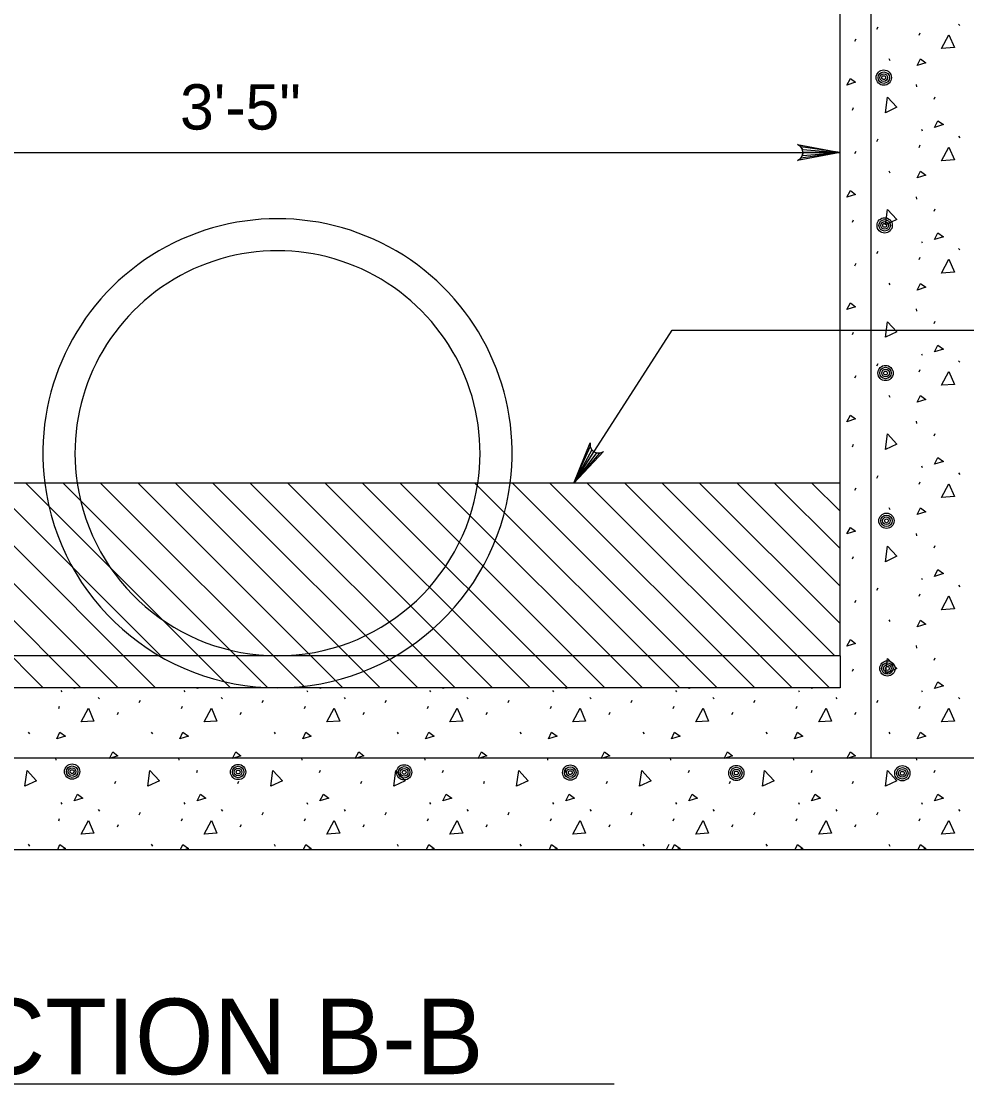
# Model space of a CAD drawing. Extents: x 2.4 to 9.7, y 1.1 to 11.2.
# Drawn here: x 3.407 to 4.657, y 8.252 to 9.657 of the extents above; entities that cross this region are included whole.
import ezdxf

# ---------------------------------------------------------------- set-up
doc = ezdxf.new("R2010")
doc.units = 0
for name, color, linetype in [('DETL-DIMS', 7, 'Continuous'), ('DETL-LINE', 7, 'Continuous'), ('DETL-NOTE', 7, 'Continuous'), ('DETL-PATT', 7, 'Continuous'), ('DETL-TITL', 7, 'Continuous')]:
    doc.layers.add(name, color=color, linetype=linetype)

msp = doc.modelspace()

# ---------------------------------------------------------------- linework, layer by layer
at = {"layer": 'DETL-DIMS'}
for p, q in [((3.0173, 9.4838), (4.49, 9.4838)), ((4.1377, 9.0465), (4.2679, 9.2486)), ((4.2679, 9.2486), (4.7805, 9.2486)), ((3.6529, 8.8182), (2.5069, 8.8182))]:
    msp.add_line(p, q, dxfattribs=at)
for points in [[(4.49, 9.4838), (4.4335, 9.4732), (4.4379, 9.4762), (4.4401, 9.48), (4.4408, 9.4838), (4.4401, 9.4876), (4.4379, 9.4914), (4.4335, 9.4944), (4.49, 9.4838), (4.4379, 9.4914), (4.4401, 9.4876), (4.49, 9.4838), (4.4408, 9.4838), (4.4401, 9.48), (4.49, 9.4838), (4.4379, 9.4762)], [(4.1377, 9.0465), (4.1594, 9.0998), (4.1596, 9.0945), (4.1615, 9.0905), (4.1644, 9.0879), (4.1679, 9.0864), (4.1723, 9.0863), (4.1772, 9.0883), (4.1377, 9.0465), (4.1723, 9.0863), (4.1679, 9.0864), (4.1377, 9.0465), (4.1644, 9.0879), (4.1615, 9.0905), (4.1377, 9.0465), (4.1596, 9.0945)]]:
    msp.add_lwpolyline(points, dxfattribs=at)
at = {"layer": 'DETL-LINE'}
for p, q in [((4.49, 8.8182), (4.49, 10.2187)), ((4.531, 8.6833), (4.531, 9.7941)), ((4.49, 9.0465), (3.0173, 9.0465)), ((4.49, 8.8182), (3.0173, 8.8182)), ((4.49, 8.8182), (4.49, 8.7758)), ((4.49, 8.7758), (3.0173, 8.7758)), ((2.9674, 8.6833), (4.531, 8.6833)), ((4.531, 8.6833), (4.6914, 8.6833)), ((2.7749, 8.5621), (4.7324, 8.5621)), ((4.2605, 8.5621), (4.264, 8.569))]:
    msp.add_line(p, q, dxfattribs=at)
for centre, radius in [((4.5476, 9.5828), 0.0101), ((4.5476, 9.5828), 0.00758), ((4.5476, 9.5828), 0.00505), ((4.5476, 9.5828), 0.00253), ((4.5488, 9.3874), 0.0101), ((4.5488, 9.3874), 0.00758), ((4.5488, 9.3874), 0.00505), ((4.5488, 9.3874), 0.00253), ((4.55, 9.1921), 0.0101), ((4.55, 9.1921), 0.00758), ((4.55, 9.1921), 0.00505), ((4.55, 9.1921), 0.00253), ((4.5512, 8.9967), 0.0101), ((4.5512, 8.9967), 0.00758), ((4.5512, 8.9967), 0.00505), ((4.5512, 8.9967), 0.00253), ((4.5524, 8.8014), 0.0101), ((4.5524, 8.8014), 0.00758), ((4.5524, 8.8014), 0.00505), ((4.5524, 8.8014), 0.00253), ((3.4746, 8.6649), 0.0101), ((3.4746, 8.6649), 0.00758), ((3.6941, 8.6644), 0.0101), ((3.6941, 8.6644), 0.00758), ((3.9136, 8.664), 0.0101), ((3.9136, 8.664), 0.00758), ((4.1332, 8.6636), 0.0101), ((4.1332, 8.6636), 0.00758), ((4.3527, 8.6631), 0.0101), ((4.3527, 8.6631), 0.00758), ((4.5722, 8.6627), 0.0101), ((3.4746, 8.6649), 0.00505), ((3.4746, 8.6649), 0.00253), ((3.6941, 8.6644), 0.00505), ((3.6941, 8.6644), 0.00253), ((3.9136, 8.664), 0.00505), ((3.9136, 8.664), 0.00253), ((4.1332, 8.6636), 0.00505), ((4.1332, 8.6636), 0.00253), ((4.3527, 8.6631), 0.00505), ((4.3527, 8.6631), 0.00253), ((4.5722, 8.6627), 0.00758), ((4.5722, 8.6627), 0.00505), ((4.5722, 8.6627), 0.00253)]:
    msp.add_circle(centre, radius, dxfattribs=at)
for radius, start, end in [(0.3102, 352.6932, 187.3068), (0.2678, 351.5277, 188.4723), (0.3102, 187.3068, 352.6932), (0.2678, 188.4723, 351.5277)]:
    msp.add_arc((3.7462, 9.086), radius, start, end, dxfattribs=at)
at = {"layer": 'DETL-PATT'}
for p, q in [((4.5385, 9.6469), (4.5401, 9.6501)), ((4.5944, 9.639), (4.5957, 9.6422)), ((4.6466, 9.6537), (4.6483, 9.6517)), ((4.5095, 9.6309), (4.5111, 9.6341)), ((4.5542, 9.608), (4.5558, 9.6056)), ((4.5904, 9.5737), (4.5908, 9.5705)), ((4.6144, 9.5544), (4.6156, 9.5576)), ((4.5063, 9.5399), (4.5075, 9.5432)), ((4.5973, 9.5146), (4.5985, 9.5126)), ((4.5385, 9.4985), (4.5401, 9.5017)), ((4.6466, 9.5053), (4.6483, 9.5033)), ((4.5095, 9.4825), (4.5111, 9.4857)), ((4.5944, 9.4905), (4.5957, 9.4937)), ((4.5542, 9.4595), (4.5558, 9.4571)), ((4.5904, 9.4253), (4.5908, 9.4221)), ((4.6144, 9.406), (4.6156, 9.4092)), ((4.5063, 9.3915), (4.5075, 9.3947)), ((4.5973, 9.3661), (4.5985, 9.3641)), ((4.5385, 9.35), (4.5401, 9.3532)), ((4.5944, 9.3421), (4.5957, 9.3453)), ((4.6466, 9.3569), (4.6483, 9.3549)), ((4.5095, 9.334), (4.5111, 9.3373)), ((4.5542, 9.3111), (4.5558, 9.3087)), ((4.5904, 9.2769), (4.5908, 9.2737)), ((4.6144, 9.2575), (4.6156, 9.2608)), ((4.5063, 9.2431), (4.5075, 9.2463)), ((4.5385, 9.2016), (4.5401, 9.2048)), ((4.5973, 9.2177), (4.5985, 9.2157)), ((4.6466, 9.2084), (4.6483, 9.2064)), ((4.5944, 9.1937), (4.5957, 9.1969)), ((4.5095, 9.1856), (4.5111, 9.1888)), ((4.5542, 9.1627), (4.5558, 9.1602)), ((4.5904, 9.1284), (4.5908, 9.1252)), ((4.6144, 9.1091), (4.6156, 9.1123)), ((4.5063, 9.0946), (4.5075, 9.0978)), ((4.5973, 9.0693), (4.5985, 9.0672)), ((4.5385, 9.0532), (4.5401, 9.0564)), ((4.6466, 9.06), (4.6483, 9.058)), ((3.1658, 9.0465), (3.4365, 8.7758)), ((3.2153, 9.0465), (3.486, 8.7758)), ((3.2648, 9.0465), (3.5355, 8.7758)), ((3.3143, 9.0465), (3.585, 8.7758)), ((3.3638, 9.0465), (3.5921, 8.8182)), ((3.4133, 9.0465), (3.684, 8.7758)), ((3.4628, 9.0465), (3.7335, 8.7758)), ((3.5123, 9.0465), (3.783, 8.7758)), ((3.5618, 9.0465), (3.8325, 8.7758)), ((3.6113, 9.0465), (3.882, 8.7758)), ((3.6608, 9.0465), (3.9315, 8.7758)), ((3.7102, 9.0465), (3.981, 8.7758)), ((3.7597, 9.0465), (4.0305, 8.7758)), ((3.8092, 9.0465), (4.08, 8.7758)), ((3.8587, 9.0465), (4.1295, 8.7758)), ((3.9082, 9.0465), (4.179, 8.7758)), ((3.9577, 9.0465), (4.2285, 8.7758)), ((4.0072, 9.0465), (4.278, 8.7758)), ((4.0567, 9.0465), (4.3275, 8.7758)), ((4.1062, 9.0465), (4.377, 8.7758)), ((4.1557, 9.0465), (4.4265, 8.7758)), ((4.2052, 9.0465), (4.476, 8.7758)), ((4.2547, 9.0465), (4.4831, 8.8182)), ((4.3042, 9.0465), (4.49, 8.8608)), ((4.3537, 9.0465), (4.49, 8.9103)), ((4.4032, 9.0465), (4.49, 8.9598)), ((4.4527, 9.0465), (4.49, 9.0092)), ((4.5095, 9.0372), (4.5111, 9.0404)), ((4.5944, 9.0452), (4.5957, 9.0484)), ((4.5542, 9.0142), (4.5558, 9.0118)), ((4.5904, 8.98), (4.5908, 8.9768)), ((4.6144, 8.9607), (4.6156, 8.9639)), ((4.5063, 8.9462), (4.5075, 8.9494)), ((4.5973, 8.9208), (4.5985, 8.9188)), ((4.6466, 8.9116), (4.6483, 8.9095)), ((4.5385, 8.9047), (4.5401, 8.9079)), ((4.5944, 8.8968), (4.5957, 8.9)), ((4.5095, 8.8887), (4.5111, 8.8919)), ((4.5542, 8.8658), (4.5558, 8.8634)), ((4.5904, 8.8316), (4.5908, 8.8283)), ((4.6144, 8.8122), (4.6156, 8.8155)), ((4.5063, 8.7977), (4.5075, 8.801)), ((3.4598, 8.7724), (3.461, 8.7704)), ((3.6223, 8.7724), (3.6235, 8.7704)), ((3.7848, 8.7724), (3.786, 8.7704)), ((3.9473, 8.7724), (3.9485, 8.7704)), ((4.1098, 8.7724), (4.111, 8.7704)), ((4.2723, 8.7724), (4.2735, 8.7704)), ((4.4348, 8.7724), (4.436, 8.7704)), ((4.5973, 8.7724), (4.5985, 8.7704)), ((3.5091, 8.7631), (3.5108, 8.7611)), ((3.5635, 8.7563), (3.5651, 8.7595)), ((3.6716, 8.7631), (3.6733, 8.7611)), ((3.726, 8.7563), (3.7276, 8.7595)), ((3.8341, 8.7631), (3.8358, 8.7611)), ((3.8885, 8.7563), (3.8901, 8.7595)), ((3.9966, 8.7631), (3.9983, 8.7611)), ((4.051, 8.7563), (4.0526, 8.7595)), ((4.1591, 8.7631), (4.1608, 8.7611)), ((4.2135, 8.7563), (4.2151, 8.7595)), ((4.3216, 8.7631), (4.3233, 8.7611)), ((4.376, 8.7563), (4.3776, 8.7595)), ((4.4841, 8.7631), (4.4858, 8.7611)), ((4.5385, 8.7563), (4.5401, 8.7595)), ((4.6466, 8.7631), (4.6483, 8.7611)), ((3.4569, 8.7483), (3.4582, 8.7516)), ((3.5345, 8.7403), (3.5361, 8.7435)), ((3.6194, 8.7483), (3.6207, 8.7516)), ((3.697, 8.7403), (3.6986, 8.7435)), ((3.7819, 8.7483), (3.7832, 8.7516)), ((3.8595, 8.7403), (3.8611, 8.7435)), ((3.9444, 8.7483), (3.9457, 8.7516)), ((4.022, 8.7403), (4.0236, 8.7435)), ((4.1069, 8.7483), (4.1082, 8.7516)), ((4.1845, 8.7403), (4.1861, 8.7435)), ((4.2694, 8.7483), (4.2707, 8.7516)), ((4.347, 8.7403), (4.3486, 8.7435)), ((4.4319, 8.7483), (4.4332, 8.7516)), ((4.5095, 8.7403), (4.5111, 8.7435)), ((4.5944, 8.7483), (4.5957, 8.7516)), ((3.4167, 8.7173), (3.4183, 8.7149)), ((3.5792, 8.7173), (3.5808, 8.7149)), ((3.7417, 8.7173), (3.7433, 8.7149)), ((3.9042, 8.7173), (3.9058, 8.7149)), ((4.0667, 8.7173), (4.0683, 8.7149)), ((4.2292, 8.7173), (4.2308, 8.7149)), ((4.3917, 8.7173), (4.3933, 8.7149)), ((4.5542, 8.7173), (4.5558, 8.7149)), ((3.4529, 8.6831), (3.4533, 8.6799)), ((3.6154, 8.6831), (3.6158, 8.6799)), ((3.7779, 8.6831), (3.7783, 8.6799)), ((3.9404, 8.6831), (3.9408, 8.6799)), ((4.1029, 8.6831), (4.1033, 8.6799)), ((4.2654, 8.6831), (4.2658, 8.6799)), ((4.4279, 8.6831), (4.4283, 8.6799)), ((4.5904, 8.6831), (4.5908, 8.6799)), ((3.4769, 8.6638), (3.4781, 8.667)), ((3.6394, 8.6638), (3.6406, 8.667)), ((3.8019, 8.6638), (3.8031, 8.667)), ((3.9644, 8.6638), (3.9656, 8.667)), ((4.1269, 8.6638), (4.1281, 8.667)), ((4.2894, 8.6638), (4.2906, 8.667)), ((4.4519, 8.6638), (4.4531, 8.667)), ((4.6144, 8.6638), (4.6156, 8.667)), ((3.5313, 8.6493), (3.5325, 8.6525)), ((3.6938, 8.6493), (3.695, 8.6525)), ((3.8563, 8.6493), (3.8575, 8.6525)), ((4.0188, 8.6493), (4.02, 8.6525)), ((4.1813, 8.6493), (4.1825, 8.6525)), ((4.3438, 8.6493), (4.345, 8.6525)), ((4.5063, 8.6493), (4.5075, 8.6525)), ((3.4598, 8.6239), (3.461, 8.6219)), ((3.5091, 8.6147), (3.5108, 8.6127)), ((3.6223, 8.6239), (3.6235, 8.6219)), ((3.6716, 8.6147), (3.6733, 8.6127)), ((3.7848, 8.6239), (3.786, 8.6219)), ((3.8341, 8.6147), (3.8358, 8.6127)), ((3.9473, 8.6239), (3.9485, 8.6219)), ((3.9966, 8.6147), (3.9983, 8.6127)), ((4.1098, 8.6239), (4.111, 8.6219)), ((4.1591, 8.6147), (4.1608, 8.6127)), ((4.2723, 8.6239), (4.2735, 8.6219)), ((4.3216, 8.6147), (4.3233, 8.6127)), ((4.4348, 8.6239), (4.436, 8.6219)), ((4.4841, 8.6147), (4.4858, 8.6127)), ((4.5973, 8.6239), (4.5985, 8.6219)), ((4.6466, 8.6147), (4.6483, 8.6127)), ((3.4569, 8.5999), (3.4582, 8.6031)), ((3.5635, 8.6078), (3.5651, 8.6111)), ((3.6194, 8.5999), (3.6207, 8.6031)), ((3.726, 8.6078), (3.7276, 8.6111)), ((3.7819, 8.5999), (3.7832, 8.6031)), ((3.8885, 8.6078), (3.8901, 8.6111)), ((3.9444, 8.5999), (3.9457, 8.6031)), ((4.051, 8.6078), (4.0526, 8.6111)), ((4.1069, 8.5999), (4.1082, 8.6031)), ((4.2135, 8.6078), (4.2151, 8.6111)), ((4.2694, 8.5999), (4.2707, 8.6031)), ((4.376, 8.6078), (4.3776, 8.6111)), ((4.4319, 8.5999), (4.4332, 8.6031)), ((4.5385, 8.6078), (4.5401, 8.6111)), ((4.5944, 8.5999), (4.5957, 8.6031)), ((3.5345, 8.5919), (3.5361, 8.5951)), ((3.697, 8.5919), (3.6986, 8.5951)), ((3.8595, 8.5919), (3.8611, 8.5951)), ((4.022, 8.5919), (4.0236, 8.5951)), ((4.1845, 8.5919), (4.1861, 8.5951)), ((4.347, 8.5919), (4.3486, 8.5951)), ((4.5095, 8.5919), (4.5111, 8.5951)), ((3.4167, 8.5689), (3.4183, 8.5665)), ((3.5792, 8.5689), (3.5808, 8.5665)), ((3.7417, 8.5689), (3.7433, 8.5665)), ((3.9042, 8.5689), (3.9058, 8.5665)), ((4.0667, 8.5689), (4.0683, 8.5665)), ((4.2292, 8.5689), (4.2308, 8.5665)), ((4.3917, 8.5689), (4.3933, 8.5665)), ((4.5542, 8.5689), (4.5558, 8.5665))]:
    msp.add_line(p, q, dxfattribs=at)
for points in [[(4.6241, 9.6213), (4.6338, 9.6394), (4.641, 9.6225), (4.6241, 9.6213)], [(4.592, 9.5987), (4.5961, 9.6076), (4.6033, 9.6023), (4.592, 9.5987)], [(4.499, 9.5729), (4.5035, 9.5818), (4.5103, 9.5766), (4.499, 9.5729)], [(4.5498, 9.5363), (4.5526, 9.5568), (4.5651, 9.5436), (4.5498, 9.5363)], [(4.6148, 9.517), (4.6193, 9.5258), (4.6265, 9.5206), (4.6148, 9.517)], [(4.6241, 9.4728), (4.6338, 9.4909), (4.641, 9.474), (4.6241, 9.4728)], [(4.592, 9.4503), (4.5961, 9.4591), (4.6033, 9.4539), (4.592, 9.4503)], [(4.499, 9.4245), (4.5035, 9.4334), (4.5103, 9.4281), (4.499, 9.4245)], [(4.5498, 9.3879), (4.5526, 9.4084), (4.5651, 9.3951), (4.5498, 9.3879)], [(4.6148, 9.3685), (4.6193, 9.3774), (4.6265, 9.3722), (4.6148, 9.3685)], [(4.6241, 9.3244), (4.6338, 9.3425), (4.641, 9.3256), (4.6241, 9.3244)], [(4.592, 9.3018), (4.5961, 9.3107), (4.6033, 9.3055), (4.592, 9.3018)], [(4.499, 9.2761), (4.5035, 9.2849), (4.5103, 9.2797), (4.499, 9.2761)], [(4.5498, 9.2394), (4.5526, 9.26), (4.5651, 9.2467), (4.5498, 9.2394)], [(4.6148, 9.2201), (4.6193, 9.229), (4.6265, 9.2237), (4.6148, 9.2201)], [(4.6241, 9.1759), (4.6338, 9.1941), (4.641, 9.1771), (4.6241, 9.1759)], [(4.592, 9.1534), (4.5961, 9.1623), (4.6033, 9.157), (4.592, 9.1534)], [(4.499, 9.1276), (4.5035, 9.1365), (4.5103, 9.1313), (4.499, 9.1276)], [(4.5498, 9.091), (4.5526, 9.1115), (4.5651, 9.0982), (4.5498, 9.091)], [(4.6148, 9.0717), (4.6193, 9.0805), (4.6265, 9.0753), (4.6148, 9.0717)], [(4.6241, 9.0275), (4.6338, 9.0456), (4.641, 9.0287), (4.6241, 9.0275)], [(4.592, 9.005), (4.5961, 9.0138), (4.6033, 9.0086), (4.592, 9.005)], [(4.499, 8.9792), (4.5035, 8.988), (4.5103, 8.9828), (4.499, 8.9792)], [(4.5498, 8.9426), (4.5526, 8.9631), (4.5651, 8.9498), (4.5498, 8.9426)], [(4.6148, 8.9232), (4.6193, 8.9321), (4.6265, 8.9269), (4.6148, 8.9232)], [(4.6241, 8.8791), (4.6338, 8.8972), (4.641, 8.8803), (4.6241, 8.8791)], [(4.592, 8.8565), (4.5961, 8.8654), (4.6033, 8.8601), (4.592, 8.8565)], [(4.499, 8.8308), (4.5035, 8.8396), (4.5103, 8.8344), (4.499, 8.8308)], [(4.5498, 8.7941), (4.5526, 8.8147), (4.5651, 8.8014), (4.5498, 8.7941)], [(4.6148, 8.7748), (4.6193, 8.7837), (4.6265, 8.7784), (4.6148, 8.7748)], [(3.4773, 8.7748), (3.4778, 8.7758)], [(3.4805, 8.7758), (3.4773, 8.7748)], [(3.6398, 8.7748), (3.6403, 8.7758)], [(3.643, 8.7758), (3.6398, 8.7748)], [(3.8023, 8.7748), (3.8028, 8.7758)], [(3.8055, 8.7758), (3.8023, 8.7748)], [(3.9648, 8.7748), (3.9653, 8.7758)], [(3.968, 8.7758), (3.9648, 8.7748)], [(4.1273, 8.7748), (4.1278, 8.7758)], [(4.1305, 8.7758), (4.1273, 8.7748)], [(4.2898, 8.7748), (4.2903, 8.7758)], [(4.293, 8.7758), (4.2898, 8.7748)], [(4.4523, 8.7748), (4.4528, 8.7758)], [(4.4555, 8.7758), (4.4523, 8.7748)], [(3.4866, 8.7306), (3.4963, 8.7487), (3.5035, 8.7318), (3.4866, 8.7306)], [(3.6491, 8.7306), (3.6588, 8.7487), (3.666, 8.7318), (3.6491, 8.7306)], [(3.8116, 8.7306), (3.8213, 8.7487), (3.8285, 8.7318), (3.8116, 8.7306)], [(3.9741, 8.7306), (3.9838, 8.7487), (3.991, 8.7318), (3.9741, 8.7306)], [(4.1366, 8.7306), (4.1463, 8.7487), (4.1535, 8.7318), (4.1366, 8.7306)], [(4.2991, 8.7306), (4.3088, 8.7487), (4.316, 8.7318), (4.2991, 8.7306)], [(4.4616, 8.7306), (4.4713, 8.7487), (4.4785, 8.7318), (4.4616, 8.7306)], [(4.6241, 8.7306), (4.6338, 8.7487), (4.641, 8.7318), (4.6241, 8.7306)], [(3.4545, 8.7081), (3.4586, 8.7169), (3.4658, 8.7117), (3.4545, 8.7081)], [(3.617, 8.7081), (3.6211, 8.7169), (3.6283, 8.7117), (3.617, 8.7081)], [(3.7795, 8.7081), (3.7836, 8.7169), (3.7908, 8.7117), (3.7795, 8.7081)], [(3.942, 8.7081), (3.9461, 8.7169), (3.9533, 8.7117), (3.942, 8.7081)], [(4.1045, 8.7081), (4.1086, 8.7169), (4.1158, 8.7117), (4.1045, 8.7081)], [(4.267, 8.7081), (4.2711, 8.7169), (4.2783, 8.7117), (4.267, 8.7081)], [(4.4295, 8.7081), (4.4336, 8.7169), (4.4408, 8.7117), (4.4295, 8.7081)], [(4.592, 8.7081), (4.5961, 8.7169), (4.6033, 8.7117), (4.592, 8.7081)], [(3.524, 8.6823), (3.5285, 8.6912), (3.5353, 8.6859), (3.524, 8.6823)], [(3.6865, 8.6823), (3.691, 8.6912), (3.6978, 8.6859), (3.6865, 8.6823)], [(3.849, 8.6823), (3.8535, 8.6912), (3.8603, 8.6859), (3.849, 8.6823)], [(4.0115, 8.6823), (4.016, 8.6912), (4.0228, 8.6859), (4.0115, 8.6823)], [(4.174, 8.6823), (4.1785, 8.6912), (4.1853, 8.6859), (4.174, 8.6823)], [(4.3365, 8.6823), (4.341, 8.6912), (4.3478, 8.6859), (4.3365, 8.6823)], [(4.499, 8.6823), (4.5035, 8.6912), (4.5103, 8.6859), (4.499, 8.6823)], [(3.4123, 8.6457), (3.4151, 8.6662), (3.4276, 8.6529), (3.4123, 8.6457)], [(3.5748, 8.6457), (3.5776, 8.6662), (3.5901, 8.6529), (3.5748, 8.6457)], [(3.7373, 8.6457), (3.7401, 8.6662), (3.7526, 8.6529), (3.7373, 8.6457)], [(3.8998, 8.6457), (3.9026, 8.6662), (3.9151, 8.6529), (3.8998, 8.6457)], [(4.0623, 8.6457), (4.0651, 8.6662), (4.0776, 8.6529), (4.0623, 8.6457)], [(4.2248, 8.6457), (4.2276, 8.6662), (4.2401, 8.6529), (4.2248, 8.6457)], [(4.3873, 8.6457), (4.3901, 8.6662), (4.4026, 8.6529), (4.3873, 8.6457)], [(4.5498, 8.6457), (4.5526, 8.6662), (4.5651, 8.6529), (4.5498, 8.6457)], [(3.4773, 8.6264), (3.4818, 8.6352), (3.489, 8.63), (3.4773, 8.6264)], [(3.6398, 8.6264), (3.6443, 8.6352), (3.6515, 8.63), (3.6398, 8.6264)], [(3.8023, 8.6264), (3.8068, 8.6352), (3.814, 8.63), (3.8023, 8.6264)], [(3.9648, 8.6264), (3.9693, 8.6352), (3.9765, 8.63), (3.9648, 8.6264)], [(4.1273, 8.6264), (4.1318, 8.6352), (4.139, 8.63), (4.1273, 8.6264)], [(4.2898, 8.6264), (4.2943, 8.6352), (4.3015, 8.63), (4.2898, 8.6264)], [(4.4523, 8.6264), (4.4568, 8.6352), (4.464, 8.63), (4.4523, 8.6264)], [(4.6148, 8.6264), (4.6193, 8.6352), (4.6265, 8.63), (4.6148, 8.6264)], [(3.4866, 8.5822), (3.4963, 8.6003), (3.5035, 8.5834), (3.4866, 8.5822)], [(3.6491, 8.5822), (3.6588, 8.6003), (3.666, 8.5834), (3.6491, 8.5822)], [(3.8116, 8.5822), (3.8213, 8.6003), (3.8285, 8.5834), (3.8116, 8.5822)], [(3.9741, 8.5822), (3.9838, 8.6003), (3.991, 8.5834), (3.9741, 8.5822)], [(4.1366, 8.5822), (4.1463, 8.6003), (4.1535, 8.5834), (4.1366, 8.5822)], [(4.2991, 8.5822), (4.3088, 8.6003), (4.316, 8.5834), (4.2991, 8.5822)], [(4.4616, 8.5822), (4.4713, 8.6003), (4.4785, 8.5834), (4.4616, 8.5822)], [(4.6241, 8.5822), (4.6338, 8.6003), (4.641, 8.5834), (4.6241, 8.5822)], [(3.4556, 8.5621), (3.4586, 8.5685), (3.4658, 8.5633), (3.4622, 8.5621)], [(3.6181, 8.5621), (3.6211, 8.5685), (3.6283, 8.5633), (3.6247, 8.5621)], [(3.7806, 8.5621), (3.7836, 8.5685), (3.7908, 8.5633), (3.7872, 8.5621)], [(3.9431, 8.5621), (3.9461, 8.5685), (3.9533, 8.5633), (3.9497, 8.5621)], [(4.1056, 8.5621), (4.1086, 8.5685), (4.1158, 8.5633), (4.1122, 8.5621)], [(4.2681, 8.5621), (4.2711, 8.5685), (4.2783, 8.5633), (4.2747, 8.5621)], [(4.4306, 8.5621), (4.4336, 8.5685), (4.4408, 8.5633), (4.4372, 8.5621)], [(4.5931, 8.5621), (4.5961, 8.5685), (4.6033, 8.5633), (4.5997, 8.5621)]]:
    msp.add_lwpolyline(points, dxfattribs=at)
at = {"layer": 'DETL-TITL'}
msp.add_line((3.14, 8.2521), (4.1911, 8.2521), dxfattribs=at)

# ---------------------------------------------------------------- texts
at = {"layer": 'DETL-NOTE'}
msp.add_text('3\'-5"', height=0.06, dxfattribs=at).set_placement((3.6173, 9.5141))
at = {"layer": 'DETL-TITL'}
msp.add_text('SECTION B-B', height=0.1, dxfattribs=at).set_placement((3.164, 8.2647))

doc.saveas('drawing.dxf')
